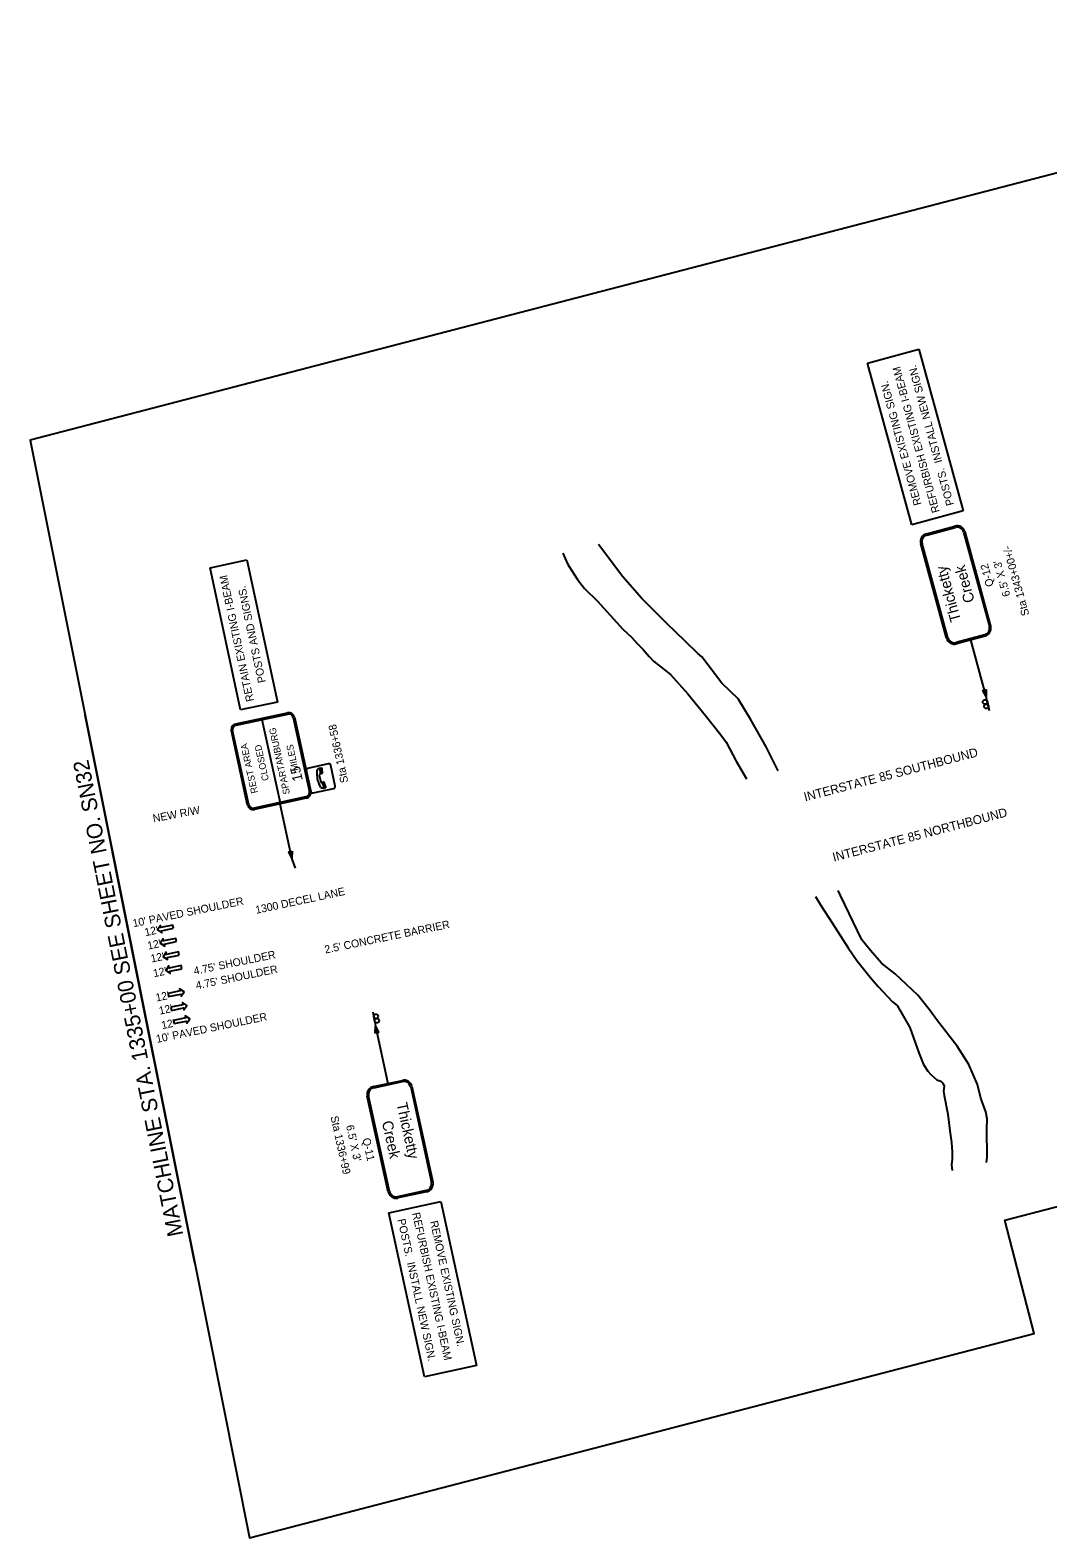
# Model space of a CAD drawing. Extents: x 1782675 to 1784334, y 1180551 to 1181928.
# Drawn here: x 1782675 to 1783586, y 1180551 to 1181900 of the extents above; entities that cross this region are included whole.
import ezdxf

# ---------------------------------------------------------------- set-up
doc = ezdxf.new("R2010")
doc.units = 0
for name, color, linetype in [('RD_EX_H2O', 7, 'Continuous'), ('RD_HC_Data', 7, 'Continuous'), ('RD_PD_FOC', 7, 'Continuous'), ('RD_PD_GR', 7, 'Continuous'), ('RD_PD_MedBWall', 7, 'Continuous'), ('RD_PD_PatLn1', 7, 'Continuous'), ('RD_SHT_MatchLine', 7, 'Continuous'), ('RD_TX_RoadID', 7, 'Continuous')]:
    doc.layers.add(name, color=color, linetype=linetype)

# ---------------------------------------------------------------- blocks, each defined once
blk = doc.blocks.new('SARRW2')
at = {"layer": 'RD_PD_GR'}
blk.add_lwpolyline([(-12, 1.2), (-12, -1.2), (-2.8, -1.2), (-2.8, -2.8), (0, 0), (-2.8, 2.8), (-2.8, 1.2)], close=True, dxfattribs=at)

msp = doc.modelspace()

# ---------------------------------------------------------------- linework, layer by layer
at = {"layer": 'RD_EX_H2O'}
for points in [[(1783151.7, 1181432.4), (1783155.9, 1181422.8), (1783159.4, 1181417), (1783164.7, 1181408.8), (1783171, 1181400.7), (1783182.6, 1181389.3), (1783205.3, 1181364.3), (1783213.3, 1181356.8), (1783218.1, 1181351.6), (1783223.6, 1181346.1), (1783228.8, 1181340), (1783232.7, 1181335.8), (1783239.5, 1181330.3), (1783248.1, 1181323.8), (1783263.4, 1181306.6), (1783279.2, 1181287), (1783293.1, 1181269.8), (1783297.9, 1181263.1), (1783306.7, 1181246.2), (1783316, 1181230.4)], [(1783344.4, 1181237.7), (1783333.7, 1181259.2), (1783319.5, 1181283.7), (1783308.4, 1181302), (1783293.9, 1181316.1), (1783276.1, 1181339.5), (1783272.5, 1181342.7), (1783261.2, 1181353.5), (1783244.6, 1181369.3), (1783222.4, 1181391.8), (1783205.4, 1181411.2), (1783183.5, 1181440)], [(1783377.8, 1181125.1), (1783382.2, 1181117.7), (1783392.8, 1181101.7), (1783407, 1181079.1), (1783414.6, 1181067.9), (1783426.6, 1181052.9), (1783433.8, 1181044.7), (1783446.7, 1181031), (1783450.7, 1181027.5), (1783462.2, 1181007.8), (1783470.1, 1180985.2), (1783474.4, 1180974.9), (1783478.4, 1180969), (1783480.9, 1180965.9), (1783486.2, 1180961), (1783489.9, 1180960), (1783491.8, 1180958.1), (1783492.8, 1180955.3), (1783492.3, 1180951.1), (1783492.9, 1180947.1), (1783496.3, 1180930.5), (1783498, 1180915.6), (1783499.4, 1180904.9), (1783500.2, 1180896.8), (1783500, 1180890.2), (1783499.4, 1180884.9), (1783500.1, 1180880.1)], [(1783530.7, 1180887), (1783531.3, 1180891.9), (1783531.2, 1180916.9), (1783531.5, 1180926.3), (1783530.1, 1180932.6), (1783525.8, 1180944.6), (1783522.6, 1180956.9), (1783515, 1180974.8), (1783504.5, 1180991.3), (1783486.9, 1181013.8), (1783479.9, 1181023.7), (1783469.3, 1181037), (1783449.1, 1181056), (1783436.7, 1181065.6), (1783426.9, 1181076.8), (1783419.3, 1181086.4), (1783400.2, 1181126), (1783398, 1181130.4)]]:
    msp.add_lwpolyline(points, dxfattribs=at)
at = {"layer": 'RD_HC_Data'}
msp.add_lwpolyline([(1784230.2, 1181398.9), (1784085.2, 1181900.3), (1784085.2, 1181900.3), (1782674.8, 1181533.5), (1782822.1, 1180797.2), (1782871.2, 1180551.3), (1783573.5, 1180734), (1783547.1, 1180835.6), (1784333.9, 1181040.2)], close=True, dxfattribs=at)
at = {"layer": 'RD_PD_PatLn1'}
for p, q in [((1783424.2, 1181602.4), (1783470.2, 1181615)), ((1783470.2, 1181615), (1783509.8, 1181470.3)), ((1783463.9, 1181457.7), (1783424.2, 1181602.4)), ((1783509.8, 1181470.3), (1783463.9, 1181457.7)), ((1783495.1, 1181356.3), (1783472, 1181440.8)), ((1782836, 1181419.3), (1782868.9, 1181426.3)), ((1782863.2, 1181292.1), (1782836, 1181419.3)), ((1782868.9, 1181426.3), (1782896.1, 1181299.1)), ((1783530.6, 1181304), (1783516.7, 1181354.7)), ((1782896.1, 1181299.1), (1782863.2, 1181292.1)), ((1783532.4, 1181295.1), (1783530.6, 1181304)), ((1783532.4, 1181295.1), (1783530.6, 1181304)), ((1783533.6, 1181291.3), (1783531.6, 1181300.1)), ((1783533.6, 1181291.3), (1783531.6, 1181300.1)), ((1782869.4, 1181206.9), (1782854.9, 1181273.3)), ((1782941.7, 1181243.8), (1782923.2, 1181239.8)), ((1782921.8, 1181237.7), (1782925.9, 1181219.2)), ((1782931.6, 1181234), (1782931.7, 1181238.3)), ((1782933.6, 1181233.7), (1782934.9, 1181227.7)), ((1782933.6, 1181233.7), (1782933.6, 1181233.7)), ((1782934.2, 1181240), (1782934.4, 1181234.9)), ((1782935.4, 1181240), (1782935.4, 1181240.1)), ((1782947.8, 1181224), (1782943.8, 1181242.4)), ((1782928, 1181217.8), (1782946.5, 1181221.8)), ((1782935.1, 1181222.7), (1782933.2, 1181226.6)), ((1782936.1, 1181227), (1782938.1, 1181222.2)), ((1782937.3, 1181227.4), (1782936.6, 1181227.1)), ((1782939.5, 1181223.3), (1782937.9, 1181227.2)), ((1782909.1, 1181159.3), (1782898.7, 1181207.9)), ((1782912.3, 1181150.4), (1782909.1, 1181159.3)), ((1782981.5, 1181022), (1782983, 1181013.2)), ((1782981.5, 1181022), (1782983, 1181013.2)), ((1782982.5, 1181018.1), (1782983.8, 1181009.2)), ((1782982.5, 1181018.1), (1782983.8, 1181009.2)), ((1782983.8, 1181009.2), (1782995, 1180957.8)), ((1783016.5, 1180955.1), (1783035.2, 1180869.6)), ((1782995.9, 1180842), (1783042.4, 1180852.2)), ((1783042.4, 1180852.2), (1783074.4, 1180705.6)), ((1783027.9, 1180695.5), (1782995.9, 1180842)), ((1783074.4, 1180705.6), (1783027.9, 1180695.5))]:
    msp.add_line(p, q, dxfattribs=at)
for points in [[(1783477, 1181449.6), (1783502.6, 1181456.6)], [(1783477.4, 1181448.4), (1783502.9, 1181455.4)], [(1783510.3, 1181451.2), (1783533.4, 1181366.7)], [(1783511.4, 1181451.5), (1783534.5, 1181367.1)], [(1783496.3, 1181356.6), (1783473.2, 1181441.1)], [(1783529.2, 1181359.4), (1783503.7, 1181352.4)], [(1783529.5, 1181358.2), (1783504, 1181351.2)], [(1782858.8, 1181279.5), (1782905.2, 1181289.6)], [(1782859.1, 1181278.3), (1782905.4, 1181288.4)], [(1782882.3, 1181283.4), (1782898.5, 1181209.1)], [(1782910.2, 1181285.4), (1782924.7, 1181218.9)], [(1782911.4, 1181285.6), (1782925.9, 1181219.2)], [(1782870.5, 1181207.1), (1782856, 1181273.6)], [(1782935.7, 1181234.9), (1782934.9, 1181234.9), (1782934.7, 1181240), (1782935.4, 1181240)], [(1782936, 1181239.6), (1782936.1, 1181235.4), (1782936.1, 1181235.4)], [(1782936.6, 1181227.1), (1782936.6, 1181227.1), (1782938.5, 1181222.4), (1782939.2, 1181222.7)], [(1782921.6, 1181214.2), (1782875.3, 1181204.1)], [(1782921.9, 1181213), (1782875.5, 1181202.9)], [(1782982.1, 1180955), (1783008, 1180960.6)], [(1782982.4, 1180953.8), (1783008.2, 1180959.5)], [(1782995.3, 1180860.9), (1782976.6, 1180946.4)], [(1782996.4, 1180861.1), (1782977.8, 1180946.7)], [(1783015.4, 1180954.9), (1783034, 1180869.3)], [(1783029.4, 1180862.2), (1783003.6, 1180856.5)], [(1783029.7, 1180861), (1783003.8, 1180855.4)]]:
    msp.add_lwpolyline(points, dxfattribs=at)
for points in [[(1783530.5, 1181310.3), (1783530.6, 1181304), (1783527.5, 1181309.5)], [(1782909.3, 1181165.6), (1782909.1, 1181159.3), (1782906.3, 1181165)], [(1782983.6, 1181002.9), (1782983.8, 1181009.2), (1782986.6, 1181003.6)]]:
    msp.add_lwpolyline(points, close=True, dxfattribs=at)
for centre in [(1783529.5, 1181299.2), (1783529.5, 1181299.2), (1783530.7, 1181295.3), (1783530.7, 1181295.3), (1782984.3, 1181017.9), (1782984.3, 1181017.9), (1782985.2, 1181014), (1782985.2, 1181014)]:
    msp.add_circle(centre, 2, dxfattribs=at)
for centre, radius, start, end in [((1783478.9, 1181442.7), 7.2, 105.3102, 195.3102), ((1783478.9, 1181442.7), 6, 105.3102, 195.3102), ((1783504.5, 1181449.6), 7.2, 15.3102, 105.3102), ((1783504.5, 1181449.6), 6, 15.3102, 105.3102), ((1783527.6, 1181365.2), 6, 285.3102, 15.3102), ((1783527.6, 1181365.2), 7.2, 285.3102, 15.3102), ((1783502.1, 1181358.2), 7.2, 195.3102, 285.3102), ((1783502.1, 1181358.2), 6, 195.3102, 285.3102), ((1782906.3, 1181284.5), 5.2, 12.3047, 102.3047), ((1782906.3, 1181284.5), 4, 12.3047, 102.3047), ((1782860, 1181274.4), 5.2, 102.3047, 192.3047), ((1782860, 1181274.4), 4, 102.3047, 192.3047), ((1782942.1, 1181242.1), 1.8, 12.3047, 102.3047), ((1782923.6, 1181238), 1.8, 102.3047, 192.3047), ((1782946.7, 1181233.4), 15.2, 177.8045, 206.8048), ((1782937.3, 1181233.2), 7.63, 127.6839, 137.8391), ((1782935.4, 1181235.7), 4.46, 105.6609, 127.6839), ((1782934.6, 1181233.9), 1.01, 102.3047, 192.3047), ((1782935.5, 1181239.5), 0.506, 2.3784, 92.3784), ((1782935.6, 1181235.4), 0.506, 272.3784, 2.3784), ((1782920.8, 1181218.1), 4, 282.3047, 12.3047), ((1782920.8, 1181218.1), 5.2, 282.3047, 12.3047), ((1782927.6, 1181219.6), 1.8, 192.3047, 282.3047), ((1782935.9, 1181227.9), 1.01, 192.3047, 282.3047), ((1782938.1, 1181229.7), 7.63, 246.7702, 256.9254), ((1782937.4, 1181226.6), 4.46, 256.9254, 278.9484), ((1782937.5, 1181227), 0.506, 22.2309, 112.2309), ((1782939, 1181223.1), 0.506, 292.2309, 22.2309), ((1782946.1, 1181223.6), 1.8, 282.3047, 12.3047), ((1782874.4, 1181208), 5.2, 192.3047, 282.3047), ((1782874.4, 1181208), 4, 192.3047, 282.3047), ((1783009.5, 1180953.6), 7.2, 12.3047, 102.3047), ((1783009.5, 1180953.6), 6, 12.3047, 102.3047), ((1782983.6, 1180948), 7.2, 102.3047, 192.3047), ((1782983.6, 1180948), 6, 102.3047, 192.3047), ((1783028.2, 1180868), 6, 282.3047, 12.3047), ((1783028.2, 1180868), 7.2, 282.3047, 12.3047), ((1783002.3, 1180862.4), 7.2, 192.3047, 282.3047), ((1783002.3, 1180862.4), 6, 192.3047, 282.3047)]:
    msp.add_arc(centre, radius, start, end, dxfattribs=at)
at = {"layer": 'RD_SHT_MatchLine'}
msp.add_lwpolyline([(1782822.1, 1180797.2), (1782773, 1181042.4), (1782724, 1181287.5)], dxfattribs=at)

# ---------------------------------------------------------------- block references
at = {"layer": 'RD_PD_GR', "yscale": 1.2000000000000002}
for p, xscale, rotation in [((1782788.8, 1181095.2), 1.2, -168.36584835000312), ((1782791.3, 1181083.3), 1.2, -168.36584835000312), ((1782793.8, 1181071.3), 1.2, -168.36584835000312), ((1782796.3, 1181059), 1.2, -168.36584835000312), ((1782812.6, 1181039.9), 1.1999999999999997, 11.634151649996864), ((1782815.1, 1181027.6), 1.1999999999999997, 11.634151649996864), ((1782817.6, 1181015.7), 1.1999999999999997, 11.634151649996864)]:
    msp.add_blockref('SARRW2', p, dxfattribs=dict(at, xscale=xscale, rotation=rotation))

# ---------------------------------------------------------------- texts
at = {"layer": 'RD_PD_FOC'}
msp.add_text('NEW R/W', height=7, rotation=10.5494, dxfattribs=at).set_placement((1782785.3, 1181191.5))
at = {"layer": 'RD_PD_MedBWall'}
for s, rotation, p in [("10' PAVED SHOULDER", 11.6342, (1782767.3, 1181097.6)), ('1300 DECEL LANE', 12.0527, (1782877.2, 1181109.6)), ("12'", 11.6342, (1782778, 1181089.6)), ("2.5' CONCRETE BARRIER", 11.6342, (1782939.1, 1181074.1)), ("12'", 11.6342, (1782780.5, 1181077.6)), ("12'", 11.6342, (1782783.4, 1181066)), ("4.75' SHOULDER", 11.6342, (1782821.9, 1181055)), ("12'", 11.6342, (1782785.6, 1181052.9)), ("4.75' SHOULDER", 11.6342, (1782823.8, 1181042)), ("12'", 11.6342, (1782787.9, 1181031.1)), ("12'", 11.6342, (1782790.8, 1181019.4)), ("10' PAVED SHOULDER", 11.6342, (1782788.3, 1180994.1)), ("12'", 11.6342, (1782793, 1181006.4))]:
    msp.add_text(s, height=7, rotation=rotation, dxfattribs=at).set_placement(p)
at = {"layer": 'RD_PD_PatLn1'}
for s, height, rotation, p in [('REFURBISH EXISTING I-BEAM', 7, 105.3103, (1783489, 1181469.5)), ('POSTS.  INSTALL NEW SIGN.', 7, 105.3103, (1783501.8, 1181475.9)), ('REMOVE EXISTING SIGN.', 7, 105.3103, (1783472.7, 1181476.1)), ('Sta 1343+00+/-', 7, 105.3103, (1783569.2, 1181377.3)), ('Thicketty', 9.6, 105.3102, (1783508.1, 1181372.3)), ('Creek', 9.6, 105.3102, (1783520.3, 1181389.4)), ('Q-12', 7, 105.3103, (1783537.4, 1181403.4)), ("6.5' X 3'", 7, 105.3103, (1783552.2, 1181394.5)), ('RETAIN EXISTING I-BEAM', 7, 102.0603, (1782875.1, 1181300.3)), ('POSTS AND SIGNS.', 7, 102.0603, (1782885.8, 1181317.1)), ('SPARTANBURG', 6, 102.3047, (1782907.4, 1181217.1)), ('Sta 1336+58', 7, 102.0603, (1782959.6, 1181227.6)), ('REST AREA', 6, 102.3047, (1782878.6, 1181218.1)), ('CLOSED', 6, 102.3047, (1782888.5, 1181229.3)), ('   MILES', 6, 102.3047, (1782916.5, 1181231.6)), ('15', 9, 102.3047, (1782918.9, 1181229.3)), ('Thicketty', 9.6, 282.3047, (1783002.7, 1180939.8)), ('Sta 1336+99', 7, 282.3048, (1782943.6, 1180928.1)), ("6.5' X 3'", 7, 282.3048, (1782957.5, 1180920)), ('Creek', 9.6, 282.3047, (1782989.6, 1180923.4)), ('Q-11', 7, 282.3048, (1782972.2, 1180908.3)), ('REFURBISH EXISTING I-BEAM', 7, 282.3048, (1783016.7, 1180841.7)), ('POSTS.  INSTALL NEW SIGN.', 7, 282.3048, (1783003.6, 1180836)), ('REMOVE EXISTING SIGN.', 7, 282.3048, (1783032.7, 1180834.3))]:
    msp.add_text(s, height=height, rotation=rotation, dxfattribs=at).set_placement(p)
at = {"layer": 'RD_SHT_MatchLine'}
msp.add_text('MATCHLINE STA. 1335+00 SEE SHEET NO. SN32', height=14, rotation=101.3102, dxfattribs=at).set_placement((1782811.9, 1180822.4))
at = {"layer": 'RD_TX_RoadID'}
for s, p in [('INTERSTATE 85 SOUTHBOUND', (1783368.5, 1181210.2)), ('INTERSTATE 85 NORTHBOUND', (1783394.2, 1181156.3))]:
    msp.add_text(s, height=8, rotation=14.6242, dxfattribs=at).set_placement(p)

doc.saveas('drawing.dxf')
